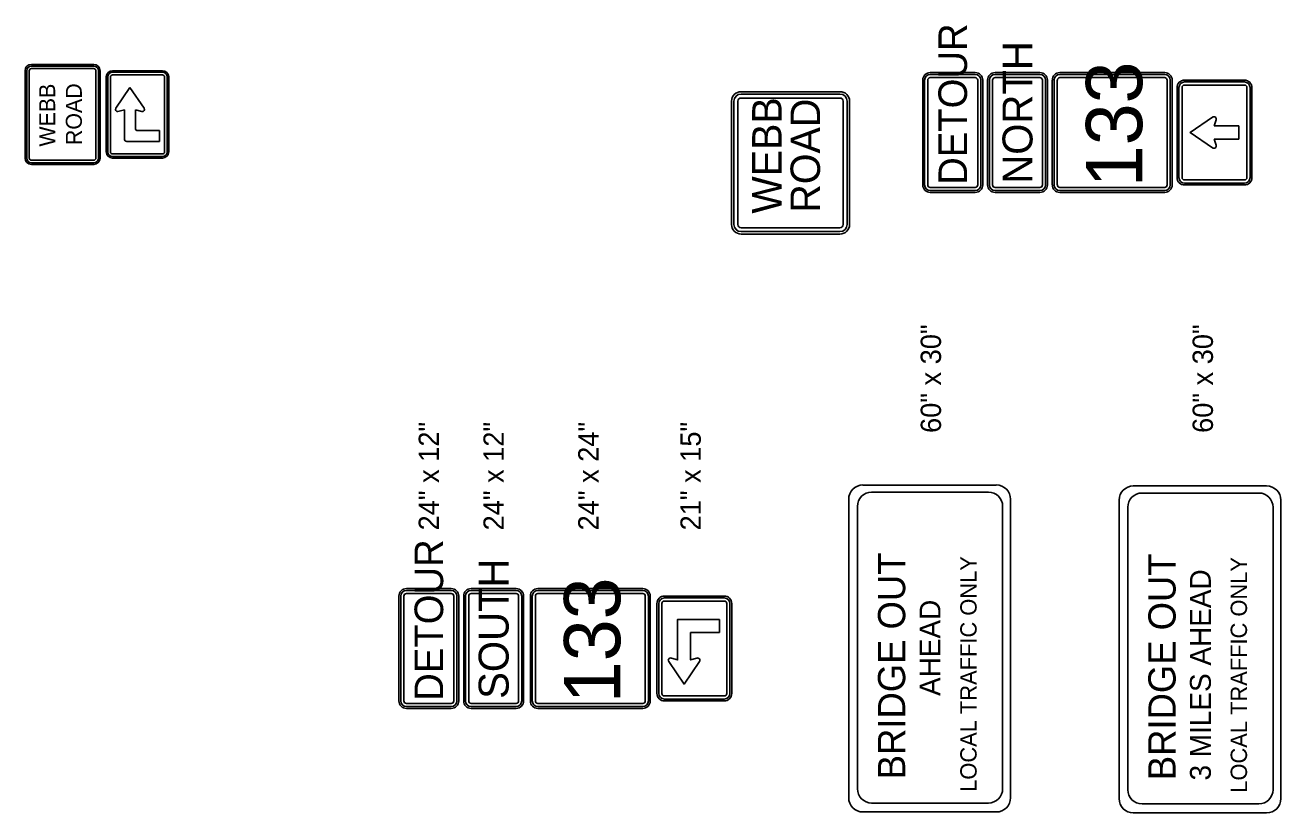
# Model space of a CAD drawing. Extents: x 1123038 to 1172987, y 554419 to 623636.
# Drawn here: x 1147873 to 1154789, y 568298 to 572635 of the extents above; entities that cross this region are included whole.
import ezdxf

# ---------------------------------------------------------------- set-up
doc = ezdxf.new("R2010")
doc.units = 0
for name, color, linetype in [('D_Text_Standard', 7, 'Continuous'), ('Default', 7, 'Continuous'), ('SIGNS TRAFFIC', 7, 'Continuous')]:
    doc.layers.add(name, color=color, linetype=linetype)

msp = doc.modelspace()

# ---------------------------------------------------------------- linework, layer by layer
at = {"layer": 'Default'}
for p, q in [((1148251.2, 572418.6), (1147907.4, 572418.6)), ((1148251.2, 572410), (1147907.4, 572410)), ((1147873, 572384.2), (1147873, 571903)), ((1147881.6, 572384.2), (1147881.6, 571903)), ((1147896, 571903), (1147896, 572384.2)), ((1147907.4, 572395.7), (1148251.2, 572395.7)), ((1148262.6, 572384.2), (1148262.6, 571903)), ((1148277, 571903), (1148277, 572384.2)), ((1148285.5, 571903), (1148285.5, 572384.2)), ((1148319.9, 572349.9), (1148319.9, 571937.4)), ((1148328.5, 572349.9), (1148328.5, 571937.4)), ((1148342.8, 571937.4), (1148342.8, 572349.9)), ((1148629.3, 572384.2), (1148354.3, 572384.2)), ((1148629.3, 572375.6), (1148354.3, 572375.6)), ((1148354.3, 572361.3), (1148629.3, 572361.3)), ((1148640.8, 572349.9), (1148640.8, 571937.4)), ((1148655.1, 571937.4), (1148655.1, 572349.9)), ((1148663.7, 571937.4), (1148663.7, 572349.9)), ((1148450.2, 572291.9), (1148371.8, 572177.7)), ((1148528.7, 572177.7), (1148450.2, 572291.9)), ((1148384.1, 572160.4), (1148420.2, 572168.7)), ((1148420.2, 572008.3), (1148420.2, 572168.7)), ((1148480.3, 572168.7), (1148516.4, 572160.4)), ((1148480.3, 572168.7), (1148480.3, 572064.1)), ((1148613.6, 571995.4), (1148433.1, 571995.4)), ((1148488.9, 572055.5), (1148613.6, 572055.5)), ((1148613.6, 572055.5), (1148613.6, 571995.4)), ((1148629.3, 571925.9), (1148354.3, 571925.9)), ((1148251.2, 571891.5), (1147907.4, 571891.5)), ((1147907.4, 571877.2), (1148251.2, 571877.2)), ((1147907.4, 571868.6), (1148251.2, 571868.6)), ((1148354.3, 571911.6), (1148629.3, 571911.6)), ((1148354.3, 571903), (1148629.3, 571903)), ((1152486.9, 570103.5), (1153221.3, 570103.5)), ((1152534.9, 570064.4), (1153178.1, 570064.4)), ((1153976, 570098.5), (1154710.3, 570098.5)), ((1154023.9, 570059.3), (1154667.1, 570059.3)), ((1152408.6, 568381.9), (1152408.6, 570025.2)), ((1153299.7, 568381.9), (1153299.7, 570025.2)), ((1153897.6, 568376.8), (1153897.6, 570020.1)), ((1154788.7, 568376.8), (1154788.7, 570020.1)), ((1152456.5, 568431.2), (1152456.5, 569986)), ((1153256.5, 568431.2), (1153256.5, 569986)), ((1153945.5, 568426.1), (1153945.5, 569981)), ((1154745.5, 568426.1), (1154745.5, 569981)), ((1152534.9, 568352.8), (1153178.1, 568352.8)), ((1154023.9, 568347.7), (1154667.1, 568347.7)), ((1152486.9, 568303.5), (1153051.2, 568303.5)), ((1153051.3, 568303.5), (1153221.3, 568303.5)), ((1153976, 568298.5), (1154540.3, 568298.5)), ((1154540.4, 568298.5), (1154710.3, 568298.5))]:
    msp.add_line(p, q, dxfattribs=at)
for centre, radius, start, end in [((1147907.4, 572384.2), 34.4, 90, 180), ((1147907.4, 572384.2), 25.8, 90, 180), ((1148251.2, 572384.2), 34.4, 0, 90), ((1148251.2, 572384.2), 25.8, 0, 90), ((1147907.4, 572384.2), 11.5, 90, 180), ((1148251.2, 572384.2), 11.5, 0, 90), ((1148354.3, 572349.9), 34.4, 90, 180), ((1148354.3, 572349.9), 25.8, 90, 180), ((1148354.3, 572349.9), 11.5, 90, 180), ((1148629.3, 572349.9), 34.4, 0, 90), ((1148629.3, 572349.9), 25.8, 0, 90), ((1148629.3, 572349.9), 11.5, 0, 90), ((1148381.5, 572171.5), 11.5, 147.7244, 282.9503), ((1148519, 572171.5), 11.5, 257.0497, 32.2757), ((1148488.9, 572064.1), 8.59, 180, 270), ((1148433.1, 572008.3), 12.9, 180, 270), ((1148354.3, 571937.4), 34.4, 180, 270), ((1148354.3, 571937.4), 25.8, 180, 270), ((1148354.3, 571937.4), 11.5, 180, 270), ((1148629.3, 571937.4), 34.4, 270, 0), ((1148629.3, 571937.4), 25.8, 270, 0), ((1148629.3, 571937.4), 11.5, 270, 0), ((1147907.4, 571903), 34.4, 180, 270), ((1147907.4, 571903), 25.8, 180, 270), ((1147907.4, 571903), 11.5, 180, 270), ((1148251.2, 571903), 34.4, 270, 0), ((1148251.2, 571903), 25.8, 270, 0), ((1148251.2, 571903), 11.5, 270, 0), ((1152486.9, 570025.2), 78.4, 90, 180), ((1152534.9, 569986), 78.4, 90, 180), ((1153178.1, 569986), 78.4, 360, 90), ((1153221.3, 570025.2), 78.4, 360, 90), ((1153976, 570020.1), 78.4, 90, 180), ((1154023.9, 569981), 78.4, 90, 180), ((1154667.1, 569981), 78.4, 360, 90), ((1154710.3, 570020.1), 78.4, 360, 90), ((1152534.9, 568431.2), 78.4, 180, 270), ((1153178.1, 568431.2), 78.4, 270, 360), ((1154023.9, 568426.1), 78.4, 180, 270), ((1154667.1, 568426.1), 78.4, 270, 360), ((1152486.9, 568381.9), 78.4, 180, 270), ((1153221.3, 568381.9), 78.4, 270, 360), ((1153976, 568376.8), 78.4, 180, 270), ((1154710.3, 568376.8), 78.4, 270, 360)]:
    msp.add_arc(centre, radius, start, end, dxfattribs=at)
at = {"layer": 'SIGNS TRAFFIC'}
for p, q in [((1154227.2, 572291.5), (1154227.2, 571796.5)), ((1154421.5, 572080.1), (1154432.3, 572113.8)), ((1154557.1, 572080.1), (1154421.5, 572080.1)), ((1154557.1, 572007.9), (1154557.1, 572080.1)), ((1154432.3, 571974.1), (1154421.5, 572007.9)), ((1154421.5, 572007.9), (1154557.1, 572007.9)), ((1151697.8, 569291.2), (1151697.8, 569363.4))]:
    msp.add_line(p, q, dxfattribs=at)
for points in [[(1152857.7, 572374), (1153105.2, 572374)], [(1152857.7, 572374), (1153105.2, 572374)], [(1152857.7, 572363.7), (1153105.2, 572363.7)], [(1153105.2, 572346.5), (1152857.7, 572346.5)], [(1153214.5, 572374), (1153462, 572374)], [(1153214.5, 572374), (1153462, 572374)], [(1153214.5, 572363.7), (1153462, 572363.7)], [(1153462, 572346.5), (1153214.5, 572346.5)], [(1153571.3, 572374), (1154148.8, 572374)], [(1153571.3, 572374), (1154148.8, 572374)], [(1153571.3, 572363.7), (1154148.8, 572363.7)], [(1154148.8, 572346.5), (1153571.3, 572346.5)], [(1152816.4, 571755.2), (1152816.4, 572332.7)], [(1152816.4, 571755.2), (1152816.4, 572332.7)], [(1152826.8, 571755.2), (1152826.8, 572332.7)], [(1152843.9, 572332.7), (1152843.9, 571755.2)], [(1153118.9, 571755.2), (1153118.9, 572332.7)], [(1153136.1, 572332.7), (1153136.1, 571755.2)], [(1153146.4, 572332.7), (1153146.4, 571755.2)], [(1153146.4, 572332.7), (1153146.4, 571755.2)], [(1153173.2, 571755.2), (1153173.2, 572332.7)], [(1153173.2, 571755.2), (1153173.2, 572332.7)], [(1153183.6, 571755.2), (1153183.6, 572332.7)], [(1153200.7, 572332.7), (1153200.7, 571755.2)], [(1153475.7, 571755.2), (1153475.7, 572332.7)], [(1153492.9, 572332.7), (1153492.9, 571755.2)], [(1153503.2, 572332.7), (1153503.2, 571755.2)], [(1153503.2, 572332.7), (1153503.2, 571755.2)], [(1153530, 571755.2), (1153530, 572332.7)], [(1153530, 571755.2), (1153530, 572332.7)], [(1153540.3, 571755.2), (1153540.3, 572332.7)], [(1153557.5, 572332.7), (1153557.5, 571755.2)], [(1154162.5, 571755.2), (1154162.5, 572332.7)], [(1154179.7, 572332.7), (1154179.7, 571755.2)], [(1154190, 572332.7), (1154190, 571755.2)], [(1154190, 572332.7), (1154190, 571755.2)], [(1154216.8, 571796.5), (1154216.8, 572291.5)], [(1154216.8, 572291.5), (1154216.8, 571796.5)], [(1154244.3, 571796.5), (1154244.3, 572291.5)], [(1154258.1, 572332.7), (1154588.1, 572332.7)], [(1154588.1, 572332.7), (1154258.1, 572332.7)], [(1154588.1, 572322.4), (1154258.1, 572322.4)], [(1154258.1, 572305.2), (1154588.1, 572305.2)], [(1154601.8, 572291.5), (1154601.8, 571796.5)], [(1154619, 571796.5), (1154619, 572291.5)], [(1154629.3, 572291.5), (1154629.3, 571796.5)], [(1154629.3, 571796.5), (1154629.3, 572291.5)], [(1151763.3, 571537.7), (1151763.3, 572216.4)], [(1151776.5, 571537.7), (1151776.5, 572216.4)], [(1151798.5, 572216.4), (1151798.5, 571537.7)], [(1151815.9, 572269), (1152360.7, 572269)], [(1151816, 572255.9), (1152360.7, 572255.9)], [(1152360.7, 572233.9), (1151816, 572233.9)], [(1152378.2, 571537.7), (1152378.2, 572216.4)], [(1152400.2, 572216.4), (1152400.2, 571537.7)], [(1152413.3, 572216.4), (1152413.3, 571537.7)], [(1154412.7, 572128.4), (1154289, 572044), (1154412.7, 571959.5)], [(1152857.7, 571741.5), (1153105.2, 571741.5)], [(1153105.2, 571724.3), (1152857.7, 571724.3)], [(1153214.5, 571741.5), (1153462, 571741.5)], [(1153462, 571724.3), (1153214.5, 571724.3)], [(1153571.3, 571741.5), (1154148.8, 571741.5)], [(1154148.8, 571724.3), (1153571.3, 571724.3)], [(1154588.1, 571782.8), (1154258.1, 571782.8)], [(1154258.1, 571765.6), (1154588.1, 571765.6)], [(1154588.1, 571755.2), (1154258.1, 571755.2)], [(1154258.1, 571755.2), (1154588.1, 571755.2)], [(1153105.2, 571714), (1152857.7, 571714)], [(1153105.2, 571714), (1152857.7, 571714)], [(1153462, 571714), (1153214.5, 571714)], [(1153462, 571714), (1153214.5, 571714)], [(1154148.8, 571714), (1153571.3, 571714)], [(1154148.8, 571714), (1153571.3, 571714)], [(1151816, 571520.2), (1152360.7, 571520.2)], [(1152360.7, 571485.1), (1151815.9, 571485.1)], [(1152360.7, 571498.3), (1151816, 571498.3)], [(1149972.7, 569533.5), (1150220.2, 569533.5)], [(1149972.7, 569533.5), (1150220.2, 569533.5)], [(1149972.7, 569523.2), (1150220.2, 569523.2)], [(1150220.2, 569506), (1149972.7, 569506)], [(1150329.5, 569533.5), (1150577, 569533.5)], [(1150329.5, 569533.5), (1150577, 569533.5)], [(1150329.5, 569523.2), (1150577, 569523.2)], [(1150577, 569506), (1150329.5, 569506)], [(1150696.8, 569533.5), (1151274.3, 569533.5)], [(1150696.8, 569533.5), (1151274.3, 569533.5)], [(1150696.8, 569523.2), (1151274.3, 569523.2)], [(1151274.3, 569506), (1150696.8, 569506)], [(1149931.4, 568914.8), (1149931.4, 569492.3)], [(1149931.4, 568914.8), (1149931.4, 569492.3)], [(1149941.8, 568914.8), (1149941.8, 569492.3)], [(1149959, 569492.3), (1149959, 568914.8)], [(1150233.9, 568914.8), (1150233.9, 569492.3)], [(1150251.1, 569492.3), (1150251.1, 568914.8)], [(1150261.4, 569492.3), (1150261.4, 568914.8)], [(1150261.4, 569492.3), (1150261.4, 568914.8)], [(1150288.2, 568914.8), (1150288.2, 569492.3)], [(1150288.2, 568914.8), (1150288.2, 569492.3)], [(1150298.6, 568914.8), (1150298.6, 569492.3)], [(1150315.8, 569492.3), (1150315.8, 568914.8)], [(1150590.7, 568914.8), (1150590.7, 569492.3)], [(1150607.9, 569492.3), (1150607.9, 568914.8)], [(1150618.2, 569492.3), (1150618.2, 568914.8)], [(1150618.2, 569492.3), (1150618.2, 568914.8)], [(1150655.6, 568914.8), (1150655.6, 569492.3)], [(1150655.6, 568914.8), (1150655.6, 569492.3)], [(1150665.9, 568914.8), (1150665.9, 569492.3)], [(1150683.1, 569492.3), (1150683.1, 568914.8)], [(1151288.1, 568914.8), (1151288.1, 569492.3)], [(1151305.3, 569492.3), (1151305.3, 568914.8)], [(1151315.6, 569492.3), (1151315.6, 568914.8)], [(1151315.6, 569492.3), (1151315.6, 568914.8)], [(1151352.3, 568956), (1151352.3, 569451)], [(1151352.3, 569451), (1151352.3, 568956)], [(1151362.6, 569451), (1151362.6, 568956)], [(1151379.8, 568956), (1151379.8, 569451)], [(1151393.5, 569492.3), (1151723.5, 569492.3)], [(1151723.5, 569492.3), (1151393.5, 569492.3)], [(1151723.5, 569482), (1151393.5, 569482)], [(1151393.5, 569464.8), (1151723.5, 569464.8)], [(1151737.3, 569451), (1151737.3, 568956)], [(1151754.5, 568956), (1151754.5, 569451)], [(1151764.8, 569451), (1151764.8, 568956)], [(1151764.8, 568956), (1151764.8, 569451)], [(1151697.8, 569363.4), (1151465.8, 569363.4), (1151465.8, 569140.2), (1151432, 569151)], [(1151571.7, 569151), (1151538, 569140.2), (1151538, 569291.2), (1151697.8, 569291.2)], [(1151417.4, 569131.4), (1151501.9, 569007.7), (1151586.3, 569131.4)], [(1149972.7, 568901.1), (1150220.2, 568901.1)], [(1150220.2, 568883.9), (1149972.7, 568883.9)], [(1150329.5, 568901.1), (1150577, 568901.1)], [(1150577, 568883.9), (1150329.5, 568883.9)], [(1150696.8, 568901), (1151274.3, 568901)], [(1151274.3, 568883.8), (1150696.8, 568883.8)], [(1151723.5, 568942.3), (1151393.5, 568942.3)], [(1151393.5, 568925.1), (1151723.5, 568925.1)], [(1151723.5, 568914.8), (1151393.5, 568914.8)], [(1151393.5, 568914.8), (1151723.5, 568914.8)], [(1150220.2, 568873.5), (1149972.7, 568873.5)], [(1150220.2, 568873.5), (1149972.7, 568873.5)], [(1150577, 568873.5), (1150329.5, 568873.5)], [(1150577, 568873.5), (1150329.5, 568873.5)], [(1151274.3, 568873.5), (1150696.8, 568873.5)], [(1151274.3, 568873.5), (1150696.8, 568873.5)]]:
    msp.add_lwpolyline(points, dxfattribs=at)
for centre, radius, start, end in [((1152857.7, 572332.7), 41.2, 90, 180), ((1152857.7, 572332.7), 41.2, 90, 180), ((1152857.7, 572332.7), 30.9, 90, 180), ((1152857.7, 572332.7), 13.7, 90, 180), ((1153105.2, 572332.7), 41.2, 360, 90), ((1153105.2, 572332.7), 41.2, 360, 90), ((1153105.2, 572332.7), 30.9, 360, 90), ((1153105.2, 572332.7), 13.7, 360, 90), ((1153214.5, 572332.7), 41.2, 90, 180), ((1153214.5, 572332.7), 41.2, 90, 180), ((1153214.5, 572332.7), 30.9, 90, 180), ((1153214.5, 572332.7), 13.7, 90, 180), ((1153462, 572332.7), 41.2, 360, 90), ((1153462, 572332.7), 41.2, 360, 90), ((1153462, 572332.7), 30.9, 360, 90), ((1153462, 572332.7), 13.7, 360, 90), ((1153571.3, 572332.7), 41.2, 90, 180), ((1153571.3, 572332.7), 41.2, 90, 180), ((1153571.3, 572332.7), 30.9, 90, 180), ((1153571.3, 572332.7), 13.7, 90, 180), ((1154148.8, 572332.7), 41.2, 360, 90), ((1154148.8, 572332.7), 41.2, 360, 90), ((1154148.8, 572332.7), 30.9, 360, 90), ((1154148.8, 572332.7), 13.7, 360, 90), ((1154258.1, 572291.5), 41.2, 90, 180), ((1154258.1, 572291.5), 41.2, 90, 180), ((1154258.1, 572291.5), 30.9, 90, 180), ((1154258.1, 572291.5), 13.7, 90, 180), ((1154588.1, 572291.5), 41.2, 360, 90), ((1154588.1, 572291.5), 41.2, 360, 90), ((1154588.1, 572291.5), 30.9, 360, 90), ((1154588.1, 572291.5), 13.7, 360, 90), ((1151815.9, 572216.4), 52.6, 90, 180), ((1151816, 572216.4), 39.4, 90, 180), ((1151816, 572216.4), 17.5, 90, 180), ((1152360.7, 572216.4), 52.6, 360, 90), ((1152360.7, 572216.4), 39.4, 360, 90), ((1152360.7, 572216.4), 17.5, 360, 90), ((1154420, 572117.8), 12.9, 342.18716, 124.32372), ((1154420, 571970.2), 12.9, 235.67628, 17.81281), ((1154258.1, 571796.5), 41.2, 180, 270), ((1154258.1, 571796.5), 41.2, 180, 270), ((1154258.1, 571796.5), 30.9, 180, 270), ((1154258.1, 571796.5), 13.7, 180, 270), ((1154588.1, 571796.5), 41.2, 270, 0), ((1154588.1, 571796.5), 41.2, 270, 0), ((1154588.1, 571796.5), 30.9, 270, 0), ((1154588.1, 571796.5), 13.7, 270, 0), ((1152857.7, 571755.2), 41.2, 180, 270), ((1152857.7, 571755.2), 41.2, 180, 270), ((1152857.7, 571755.2), 30.9, 180, 270), ((1152857.7, 571755.2), 13.7, 180, 270), ((1153105.2, 571755.2), 41.2, 270, 360), ((1153105.2, 571755.2), 41.2, 270, 360), ((1153105.2, 571755.2), 30.9, 270, 360), ((1153105.2, 571755.2), 13.7, 270, 360), ((1153214.5, 571755.2), 41.2, 180, 270), ((1153214.5, 571755.2), 41.2, 180, 270), ((1153214.5, 571755.2), 30.9, 180, 270), ((1153214.5, 571755.2), 13.7, 180, 270), ((1153462, 571755.2), 41.2, 270, 360), ((1153462, 571755.2), 41.2, 270, 360), ((1153462, 571755.2), 30.9, 270, 360), ((1153462, 571755.2), 13.7, 270, 360), ((1153571.3, 571755.2), 41.2, 180, 270), ((1153571.3, 571755.2), 41.2, 180, 270), ((1153571.3, 571755.2), 30.9, 180, 270), ((1153571.3, 571755.2), 13.7, 180, 270), ((1154148.8, 571755.2), 41.2, 270, 360), ((1154148.8, 571755.2), 41.2, 270, 360), ((1154148.8, 571755.2), 30.9, 270, 360), ((1154148.8, 571755.2), 13.7, 270, 360), ((1151815.9, 571537.7), 52.6, 180, 270), ((1151816, 571537.7), 39.4, 180, 270), ((1151816, 571537.7), 17.5, 180, 270), ((1152360.7, 571537.7), 52.6, 270, 0), ((1152360.7, 571537.7), 39.4, 270, 0), ((1152360.7, 571537.7), 17.5, 270, 0), ((1149972.7, 569492.3), 41.2, 90, 180), ((1149972.7, 569492.3), 41.2, 90, 180), ((1149972.7, 569492.3), 30.9, 90, 180), ((1149972.7, 569492.3), 13.7, 90, 180), ((1150220.2, 569492.3), 41.2, 360, 90), ((1150220.2, 569492.3), 41.2, 360, 90), ((1150220.2, 569492.3), 30.9, 360, 90), ((1150220.2, 569492.3), 13.7, 360, 90), ((1150329.5, 569492.3), 41.2, 90, 180), ((1150329.5, 569492.3), 41.2, 90, 180), ((1150329.5, 569492.3), 30.9, 90, 180), ((1150329.5, 569492.3), 13.7, 90, 180), ((1150577, 569492.3), 41.2, 360, 90), ((1150577, 569492.3), 41.2, 360, 90), ((1150577, 569492.3), 30.9, 360, 90), ((1150577, 569492.3), 13.7, 360, 90), ((1150696.8, 569492.3), 41.2, 90, 180), ((1150696.8, 569492.3), 41.2, 90, 180), ((1150696.8, 569492.3), 30.9, 90, 180), ((1150696.8, 569492.3), 13.7, 90, 180), ((1151274.3, 569492.3), 41.2, 360, 90), ((1151274.3, 569492.3), 41.2, 360, 90), ((1151274.3, 569492.3), 30.9, 360, 90), ((1151274.3, 569492.3), 13.7, 360, 90), ((1151393.5, 569451), 41.2, 90, 180), ((1151393.5, 569451), 41.2, 90, 180), ((1151393.5, 569451), 30.9, 90, 180), ((1151393.5, 569451), 13.7, 90, 180), ((1151723.5, 569451), 41.2, 360, 90), ((1151723.5, 569451), 41.2, 360, 90), ((1151723.5, 569451), 30.9, 360, 90), ((1151723.5, 569451), 13.7, 360, 90), ((1151428.1, 569138.7), 12.9, 72.18716, 214.32372), ((1151575.7, 569138.7), 12.9, 325.67628, 107.81281), ((1151393.5, 568956), 41.2, 180, 270), ((1151393.5, 568956), 41.2, 180, 270), ((1151393.5, 568956), 30.9, 180, 270), ((1151393.5, 568956), 13.7, 180, 270), ((1151723.5, 568956), 41.2, 270, 0), ((1151723.5, 568956), 41.2, 270, 0), ((1151723.5, 568956), 30.9, 270, 0), ((1151723.5, 568956), 13.7, 270, 0), ((1149972.7, 568914.8), 41.2, 180, 270), ((1149972.7, 568914.8), 41.2, 180, 270), ((1149972.7, 568914.8), 30.9, 180, 270), ((1149972.7, 568914.8), 13.7, 180, 270), ((1150220.2, 568914.8), 41.2, 270, 360), ((1150220.2, 568914.8), 41.2, 270, 360), ((1150220.2, 568914.8), 30.9, 270, 360), ((1150220.2, 568914.8), 13.7, 270, 360), ((1150329.5, 568914.8), 41.2, 180, 270), ((1150329.5, 568914.8), 41.2, 180, 270), ((1150329.5, 568914.8), 30.9, 180, 270), ((1150329.5, 568914.8), 13.7, 180, 270), ((1150577, 568914.8), 41.2, 270, 360), ((1150577, 568914.8), 41.2, 270, 360), ((1150577, 568914.8), 30.9, 270, 360), ((1150577, 568914.8), 13.7, 270, 360), ((1150696.8, 568914.8), 41.2, 180, 270), ((1150696.8, 568914.8), 41.2, 180, 270), ((1150696.8, 568914.8), 30.9, 180, 270), ((1150696.8, 568914.8), 13.7, 180, 270), ((1151274.3, 568914.8), 41.2, 270, 360), ((1151274.3, 568914.8), 41.2, 270, 360), ((1151274.3, 568914.8), 30.9, 270, 360), ((1151274.3, 568914.8), 13.7, 270, 360)]:
    msp.add_arc(centre, radius, start, end, dxfattribs=at)

# ---------------------------------------------------------------- texts
at = {"layer": 'D_Text_Standard'}
for s, p in [('60" x 30"', (1152917, 570390.1)), ('60" x 30"', (1154414.6, 570390.3)), ('24" x 12"', (1150152.4, 569853.5)), ('24" x 12"', (1150509.2, 569853.5)), ('24" x 24"', (1151031, 569853.5)), ('21" x 15"', (1151594.1, 569853.5))]:
    msp.add_text(s, height=111.99, rotation=90, dxfattribs=at).set_placement(p)
at = {"layer": 'Default'}
for s, height, p in [('WEBB', 88, (1148038.7, 571966.5)), ('ROAD', 88, (1148185.4, 571974.9)), ('BRIDGE OUT', 150, (1152719.9, 568483.6)), ('BRIDGE OUT', 150, (1154208.9, 568478.5)), ('LOCAL TRAFFIC ONLY', 90, (1153113.1, 568414.5)), ('LOCAL TRAFFIC ONLY', 90, (1154602.1, 568409.5)), ('3 MILES AHEAD', 115, (1154403, 568476.9)), ('AHEAD', 115, (1152914, 568942))]:
    msp.add_text(s, height=height, rotation=90, dxfattribs=at).set_placement(p)
at = {"layer": 'SIGNS TRAFFIC'}
for s, height, p in [('DETOUR', 157.5, (1153060.2, 571755.9)), ('NORTH', 165, (1153420.7, 571762.3)), ('133', 310, (1154025, 571743.3)), ('WEBB', 162.5, (1152039.3, 571597.8)), ('ROAD', 162.5, (1152250.8, 571602.7)), ('DETOUR', 157.5, (1150175.2, 568915.5)), ('SOUTH', 165, (1150535.8, 568926.3)), ('133', 310, (1151150.6, 568902.9))]:
    msp.add_text(s, height=height, rotation=90, dxfattribs=at).set_placement(p)

doc.saveas('drawing.dxf')
